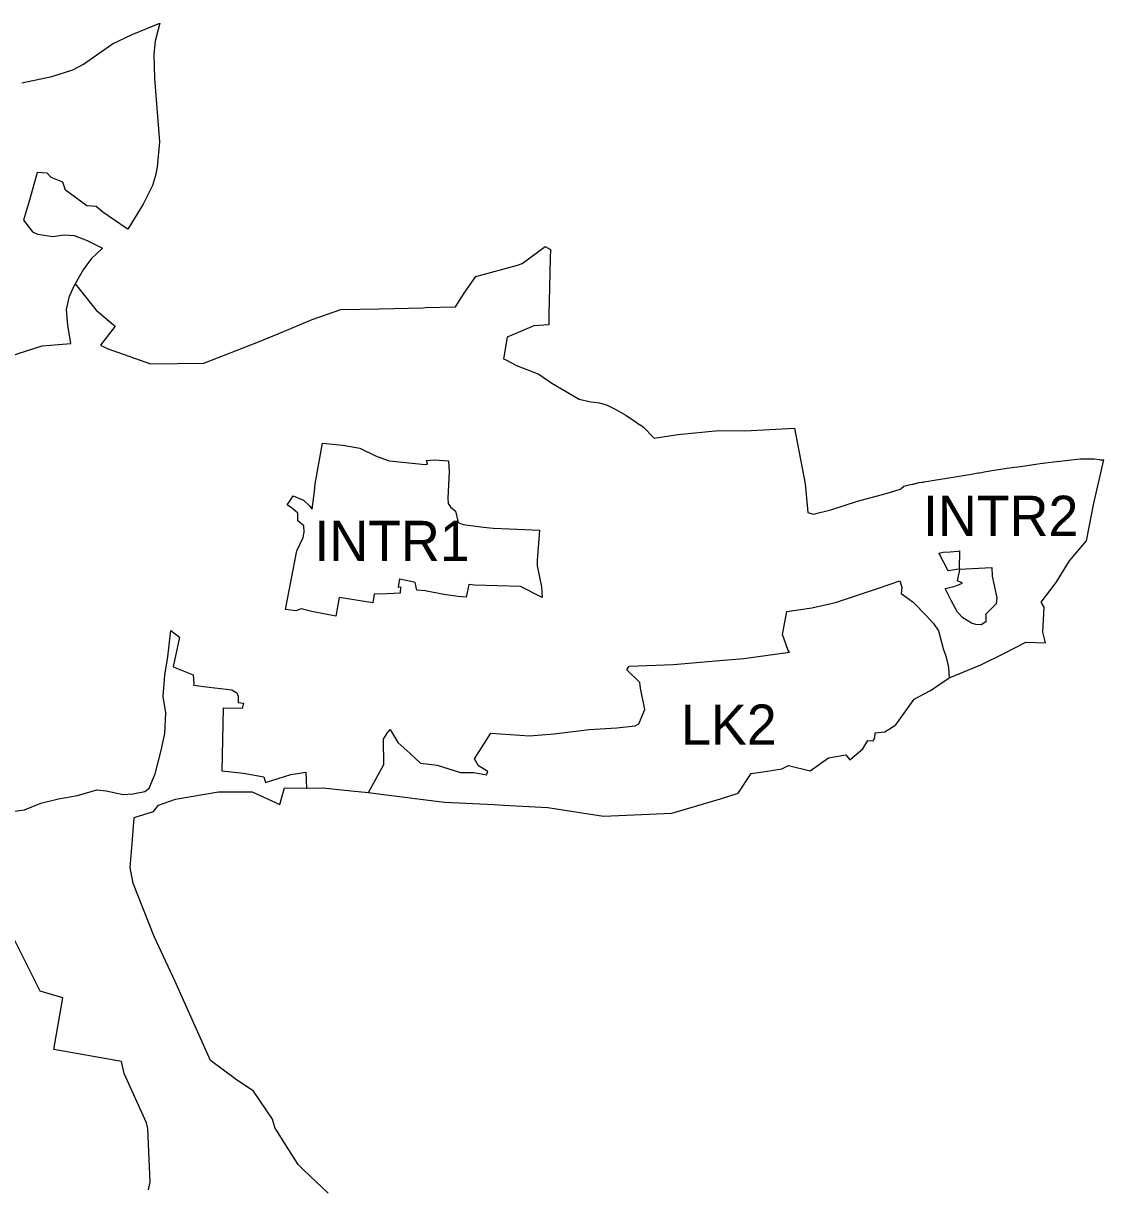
# Model space of a CAD drawing. Extents: x -754919 to -751903, y -1143879 to -1139906.
# Drawn here: x -753784 to -751903, y -1141930 to -1139906 of the extents above; entities that cross this region are included whole.
import ezdxf

# ---------------------------------------------------------------- set-up
doc = ezdxf.new("R2010")
doc.units = 0
for name, color, linetype in [('Vrstva 13', 7, 'Continuous'), ('Vrstva 2', 7, 'Continuous'), ('Vrstva 4', 7, 'Continuous'), ('Vrstva 6', 7, 'Continuous')]:
    doc.layers.add(name, color=color, linetype=linetype)

msp = doc.modelspace()

# ---------------------------------------------------------------- linework, layer by layer
at = {"layer": 'Vrstva 13'}
for p, q in [((-753594.49, -1139925.95), (-753546, -1139906.33)), ((-753546, -1139906.33), (-753554.18, -1139937.38)), ((-753679.34, -1139977.81), (-753628.6, -1139942.29)), ((-753628.6, -1139942.29), (-753594.49, -1139925.95)), ((-753554.18, -1139937.38), (-753556.53, -1139960.2)), ((-753556.53, -1139960.2), (-753555.59, -1140002.25)), ((-753697.41, -1139987.55), (-753679.34, -1139977.81)), ((-753786.41, -1140010.3), (-753733.98, -1139998.76)), ((-753733.98, -1139998.76), (-753697.41, -1139987.55)), ((-753555.59, -1140002.25), (-753546.66, -1140112.83)), ((-753546.66, -1140112.83), (-753550.87, -1140157.09)), ((-753759.52, -1140166.02), (-753773.33, -1140214.43)), ((-753742.36, -1140167.45), (-753759.52, -1140166.02)), ((-753550.87, -1140157.09), (-753553.62, -1140171.36)), ((-753735.49, -1140174.73), (-753742.36, -1140167.45)), ((-753715.04, -1140182.67), (-753735.49, -1140174.73)), ((-753710.41, -1140197.1), (-753715.04, -1140182.67)), ((-753553.62, -1140171.36), (-753559.2, -1140188.9)), ((-753673.16, -1140224.2), (-753710.41, -1140197.1)), ((-753559.2, -1140188.9), (-753575.24, -1140221.13)), ((-753773.33, -1140214.43), (-753783.31, -1140249.29)), ((-753656.91, -1140225.41), (-753673.16, -1140224.2)), ((-753645.46, -1140235.37), (-753656.91, -1140225.41)), ((-753575.24, -1140221.13), (-753602.16, -1140264.61)), ((-753604.73, -1140262.87), (-753645.46, -1140235.37)), ((-753783.31, -1140249.29), (-753768.02, -1140269.15)), ((-753602.16, -1140264.61), (-753604.73, -1140262.87)), ((-753768.02, -1140269.15), (-753759.37, -1140273.27)), ((-753759.37, -1140273.27), (-753732.61, -1140277.4)), ((-753732.61, -1140277.4), (-753712.47, -1140274.49)), ((-753712.47, -1140274.49), (-753695.07, -1140275.67)), ((-753695.07, -1140275.67), (-753672.72, -1140284.4)), ((-753672.72, -1140284.4), (-753646.26, -1140297.83)), ((-753646.26, -1140297.83), (-753665.53, -1140316.44)), ((-752915.15, -1140324.22), (-752874.93, -1140295.15)), ((-752874.93, -1140295.15), (-752866.09, -1140300.36)), ((-752866.09, -1140300.36), (-752866.42, -1140314.92)), ((-753665.53, -1140316.44), (-753679.47, -1140335.74)), ((-752996.14, -1140347.33), (-752923.33, -1140327.21)), ((-752923.33, -1140327.21), (-752915.15, -1140324.22)), ((-752866.42, -1140314.92), (-752867, -1140340.25)), ((-753679.47, -1140335.74), (-753693.42, -1140360)), ((-753016.17, -1140376.35), (-752996.14, -1140347.33)), ((-752867, -1140340.25), (-752868.14, -1140390.58)), ((-753693.42, -1140360), (-753684.23, -1140371.56)), ((-753684.23, -1140371.56), (-753657.16, -1140405.61)), ((-753031.34, -1140400.09), (-753016.17, -1140376.35)), ((-753657.16, -1140405.61), (-753626.85, -1140431.3)), ((-753280.74, -1140422.14), (-753230.77, -1140404.54)), ((-753230.77, -1140404.54), (-753164.62, -1140403.24)), ((-753164.62, -1140403.24), (-753087.86, -1140401.43)), ((-753087.86, -1140401.43), (-753084.06, -1140401.34)), ((-753084.06, -1140401.34), (-753031.34, -1140400.09)), ((-752868.14, -1140390.58), (-752868.6, -1140410.75)), ((-753336.01, -1140445.01), (-753280.74, -1140422.14)), ((-752868.6, -1140410.75), (-752869.07, -1140431.37)), ((-753624.11, -1140433.63), (-753649.36, -1140466.63)), ((-753626.85, -1140431.3), (-753624.11, -1140433.63)), ((-753377.25, -1140462.18), (-753336.01, -1140445.01)), ((-752894.72, -1140433.16), (-752941.33, -1140453)), ((-752869.07, -1140431.37), (-752894.72, -1140433.16)), ((-753649.36, -1140466.63), (-753638.09, -1140472.67)), ((-753469.49, -1140497.93), (-753377.25, -1140462.18)), ((-752941.33, -1140453), (-752947.7, -1140490.21)), ((-753638.09, -1140472.67), (-753562.69, -1140498.88)), ((-753562.69, -1140498.88), (-753469.49, -1140497.93)), ((-752947.7, -1140490.21), (-752943.5, -1140492.45)), ((-752943.5, -1140492.45), (-752924.98, -1140502.31)), ((-752924.98, -1140502.31), (-752885.95, -1140517.36)), ((-752885.95, -1140517.36), (-752863.41, -1140532.87)), ((-752863.41, -1140532.87), (-752815.79, -1140560.49)), ((-752815.79, -1140560.49), (-752795.75, -1140565.11)), ((-752795.75, -1140565.11), (-752780.29, -1140566.9)), ((-752780.29, -1140566.9), (-752767.16, -1140571.19)), ((-752767.16, -1140571.19), (-752753.13, -1140577.78)), ((-752753.13, -1140577.78), (-752734.43, -1140588.57)), ((-752734.43, -1140588.57), (-752716.77, -1140600.62)), ((-752716.77, -1140600.62), (-752713.69, -1140602.72)), ((-752713.69, -1140602.72), (-752707.09, -1140607.22)), ((-752707.09, -1140607.22), (-752703.83, -1140609.44)), ((-752703.83, -1140609.44), (-752685.4, -1140628.65)), ((-752527.68, -1140615.88), (-752441.03, -1140610.83)), ((-752441.03, -1140610.83), (-752422.64, -1140708.22)), ((-752685.4, -1140628.65), (-752644, -1140622.18)), ((-752644, -1140622.18), (-752572.98, -1140615.27)), ((-752572.98, -1140615.27), (-752527.68, -1140615.88)), ((-752013.19, -1140672.6), (-752007.81, -1140671.83)), ((-752007.81, -1140671.83), (-752004.62, -1140671.46)), ((-752004.62, -1140671.46), (-751943.59, -1140664.35)), ((-751943.59, -1140664.35), (-751919.21, -1140664.56)), ((-751919.86, -1140741.61), (-751902.51, -1140666.4)), ((-751919.21, -1140664.56), (-751910.79, -1140665.62)), ((-751910.79, -1140665.62), (-751908.26, -1140665.94)), ((-751908.26, -1140665.94), (-751902.51, -1140666.4)), ((-752147.19, -1140693.27), (-752129.95, -1140690.44)), ((-752129.95, -1140690.44), (-752124.87, -1140689.6)), ((-752124.87, -1140689.6), (-752120.42, -1140688.87)), ((-752120.42, -1140688.87), (-752118.97, -1140688.63)), ((-752118.97, -1140688.63), (-752115.46, -1140688.07)), ((-752115.46, -1140688.07), (-752110.72, -1140687.31)), ((-752110.72, -1140687.31), (-752093.14, -1140684.48)), ((-752093.14, -1140684.48), (-752074.94, -1140681.56)), ((-752074.94, -1140681.56), (-752071.19, -1140680.96)), ((-752071.19, -1140680.96), (-752062.09, -1140679.65)), ((-752062.09, -1140679.65), (-752047.56, -1140677.55)), ((-752047.56, -1140677.55), (-752020.55, -1140673.66)), ((-752020.55, -1140673.66), (-752013.19, -1140672.6)), ((-752422.64, -1140708.22), (-752417.81, -1140757.62)), ((-752255.48, -1140716.14), (-752250.42, -1140711.96)), ((-752250.42, -1140711.96), (-752239.12, -1140709.38)), ((-752239.12, -1140709.38), (-752235.95, -1140708.65)), ((-752235.95, -1140708.65), (-752234.49, -1140708.32)), ((-752234.49, -1140708.32), (-752224.01, -1140705.92)), ((-752224.01, -1140705.92), (-752219.4, -1140705.16)), ((-752219.4, -1140705.16), (-752217.26, -1140704.81)), ((-752217.26, -1140704.81), (-752215.45, -1140704.51)), ((-752215.45, -1140704.51), (-752211.97, -1140703.94)), ((-752211.97, -1140703.94), (-752207.74, -1140703.24)), ((-752207.74, -1140703.24), (-752201.24, -1140702.17)), ((-752201.24, -1140702.17), (-752197.74, -1140701.59)), ((-752197.74, -1140701.59), (-752164.99, -1140696.2)), ((-752164.99, -1140696.2), (-752147.19, -1140693.27)), ((-752331.56, -1140738.32), (-752281.55, -1140725.04)), ((-752281.55, -1140725.04), (-752257.08, -1140717.47)), ((-752257.08, -1140717.47), (-752255.48, -1140716.14)), ((-752377.84, -1140753), (-752331.56, -1140738.32)), ((-751932.42, -1140806.95), (-751919.86, -1140741.61)), ((-752417.81, -1140757.62), (-752408.61, -1140760.55)), ((-752408.61, -1140760.55), (-752377.84, -1140753)), ((-751961.94, -1140841.77), (-751932.42, -1140806.95)), ((-751985.4, -1140879.61), (-751961.94, -1140841.77)), ((-752011.65, -1140914.05), (-751985.4, -1140879.61)), ((-752006.25, -1140922.82), (-752011.65, -1140914.05)), ((-752008.67, -1140966.42), (-752006.25, -1140922.82)), ((-752003.83, -1140984.73), (-752008.67, -1140966.42)), ((-752076.66, -1141003.29), (-752038.37, -1140983.78)), ((-752038.37, -1140983.78), (-752003.83, -1140984.73)), ((-752116.68, -1141023), (-752076.66, -1141003.29)), ((-752171.56, -1141045.76), (-752116.68, -1141023)), ((-752204.35, -1141067.64), (-752171.56, -1141045.76)), ((-752232.88, -1141082.54), (-752204.35, -1141067.64)), ((-752264.77, -1141127.4), (-752232.88, -1141082.54)), ((-752283.9, -1141139.69), (-752264.77, -1141127.4)), ((-752321.87, -1141169.45), (-752313.28, -1141154.81)), ((-752313.28, -1141154.81), (-752304.08, -1141155.04)), ((-752304.08, -1141155.04), (-752301.13, -1141150.16)), ((-752301.13, -1141150.16), (-752300.56, -1141141.33)), ((-752300.56, -1141141.33), (-752283.9, -1141139.69)), ((-752344.63, -1141188.12), (-752321.87, -1141169.45)), ((-752413.63, -1141207.48), (-752382.04, -1141185.18)), ((-752382.04, -1141185.18), (-752351.86, -1141179.62)), ((-752351.86, -1141179.62), (-752344.63, -1141188.12)), ((-752539.4, -1141246.36), (-752516.76, -1141212.45)), ((-752516.76, -1141212.45), (-752491.94, -1141208.63)), ((-752491.94, -1141208.63), (-752462.88, -1141204.16)), ((-752462.88, -1141204.16), (-752451.7, -1141198.36)), ((-752451.7, -1141198.36), (-752413.63, -1141207.48)), ((-753337.06, -1141266.35), (-753329.01, -1141237.09)), ((-753329.01, -1141237.09), (-753290.83, -1141237.76)), ((-753290.83, -1141237.76), (-753262.57, -1141237.39)), ((-753262.57, -1141237.39), (-753212.76, -1141242.25)), ((-753548.27, -1141267.42), (-753518.61, -1141257)), ((-753518.61, -1141257), (-753443.73, -1141244.32)), ((-753443.73, -1141244.32), (-753385.57, -1141243.79)), ((-753385.57, -1141243.79), (-753337.06, -1141266.35)), ((-753212.76, -1141242.25), (-753182.94, -1141245.36)), ((-753182.94, -1141245.36), (-753161.13, -1141247.93)), ((-753161.13, -1141247.93), (-753050.75, -1141261.77)), ((-752654.45, -1141281.32), (-752569.69, -1141256.1)), ((-752569.69, -1141256.1), (-752539.4, -1141246.36)), ((-753591.07, -1141288.95), (-753557.15, -1141278.12)), ((-753557.15, -1141278.12), (-753548.27, -1141267.42)), ((-753050.75, -1141261.77), (-752963.8, -1141266.25)), ((-752963.8, -1141266.25), (-752947.47, -1141267.09)), ((-752947.47, -1141267.09), (-752870.43, -1141271.06)), ((-752870.43, -1141271.06), (-752773.66, -1141286.63)), ((-753593.74, -1141327.11), (-753591.63, -1141296.97)), ((-753591.63, -1141296.97), (-753591.07, -1141288.95)), ((-752773.66, -1141286.63), (-752654.45, -1141281.32)), ((-753598.07, -1141375.75), (-753593.74, -1141327.11)), ((-753594.98, -1141391.33), (-753598.07, -1141375.75)), ((-753593.37, -1141399.46), (-753594.98, -1141391.33)), ((-753592.94, -1141401.61), (-753593.37, -1141399.46)), ((-753556.28, -1141495.6), (-753592.94, -1141401.61)), ((-753519.49, -1141574.11), (-753556.28, -1141495.6)), ((-753457.91, -1141711.51), (-753519.49, -1141574.11)), ((-753414.97, -1141743.82), (-753457.91, -1141711.51)), ((-753382.94, -1141765.31), (-753414.97, -1141743.82)), ((-753349.69, -1141813.83), (-753382.94, -1141765.31)), ((-753347.97, -1141820.06), (-753349.69, -1141813.83)), ((-753346.28, -1141826.13), (-753347.97, -1141820.06)), ((-753345.7, -1141828.24), (-753346.28, -1141826.13)), ((-753329.73, -1141854.5), (-753345.7, -1141828.24)), ((-753305.04, -1141892.8), (-753329.73, -1141854.5)), ((-753303.66, -1141894.23), (-753305.04, -1141892.8)), ((-753296.14, -1141902.04), (-753303.66, -1141894.23)), ((-753252.88, -1141942.87), (-753296.14, -1141902.04))]:
    msp.add_line(p, q, dxfattribs=at)
at = {"layer": 'Vrstva 2'}
msp.add_line((-752153.47, -1140824.76), (-752154.23, -1140856.39), dxfattribs=at)
for points in [[(-753313.75, -1140728.99), (-753295.92, -1140736.15), (-753284.73, -1140746.9), (-753280.73, -1140752.22), (-753276.98, -1140721.56), (-753275.54, -1140708.13), (-753263.11, -1140637.4), (-753227.56, -1140640.75), (-753197.92, -1140646.11), (-753195.47, -1140647.24), (-753170.73, -1140659.07), (-753148.76, -1140667.4), (-753146.13, -1140668.09), (-753084.33, -1140674.13), (-753080.12, -1140673.74), (-753081.55, -1140667.22), (-753067.68, -1140666.26), (-753043.34, -1140668.11)], [(-753043.34, -1140668.11), (-753042.4, -1140686.86), (-753044.93, -1140732.78), (-753043.91, -1140742.05), (-753040.04, -1140748.29), (-753031.42, -1140755.55), (-753026.65, -1140775.18), (-753017.69, -1140778.75), (-752982.62, -1140783.31), (-752965.73, -1140785.21), (-752937.94, -1140786.41), (-752924.5, -1140787.04), (-752911.06, -1140787.35), (-752897.9, -1140787.97), (-752884.87, -1140788.59)], [(-753296.52, -1140801.56), (-753294.93, -1140791.98), (-753295.63, -1140781.28), (-753305.77, -1140772.11), (-753305.91, -1140759.01), (-753314.44, -1140751.47), (-753324.51, -1140744.47), (-753320.63, -1140738.5), (-753313.75, -1140728.99)], [(-752884.87, -1140788.59), (-752888.93, -1140841.16), (-752889.13, -1140850.97), (-752881.69, -1140887.43), (-752880.26, -1140905.84), (-752918.14, -1140886.54), (-752997.99, -1140884.58), (-753008.05, -1140883.34)], [(-753239.95, -1140938.18), (-753281.58, -1140930.1), (-753299.82, -1140925.45), (-753309.54, -1140929.26), (-753327.14, -1140926.46), (-753307.39, -1140824.44), (-753296.52, -1140801.56)], [(-752154.27, -1140856.42), (-752158.13, -1140857.28), (-752173.45, -1140859.58), (-752188.69, -1140830.22), (-752189.59, -1140828.48), (-752182.14, -1140827.07), (-752170.24, -1140826.27), (-752156.43, -1140824.97), (-752153.47, -1140824.76)], [(-752154.23, -1140856.39), (-752097.57, -1140853.76), (-752096.81, -1140868.44), (-752088.67, -1140906.23), (-752090.01, -1140917.06), (-752107.79, -1140934.64), (-752108.13, -1140948.01), (-752115.83, -1140953.69), (-752125.08, -1140953.05), (-752132.56, -1140950.41), (-752147.71, -1140940.93), (-752157.19, -1140931.45), (-752168.4, -1140910.83), (-752178.42, -1140890.27), (-752163.36, -1140886.9), (-752157.33, -1140884.24), (-752148.27, -1140880.81), (-752157.17, -1140876.99), (-752153.04, -1140857.92), (-752154.27, -1140856.42)], [(-753008.05, -1140883.34), (-753012.9, -1140905.38), (-753026.62, -1140903.89), (-753051.55, -1140900.48), (-753083.85, -1140894.51), (-753098.72, -1140892.92), (-753101.61, -1140879.94), (-753111.61, -1140877.49), (-753128.62, -1140873.67), (-753129.01, -1140873.58), (-753131.27, -1140887.71), (-753127.34, -1140887.31), (-753127.4, -1140898.4), (-753150.07, -1140899.22), (-753173.15, -1140900.28), (-753175.16, -1140914.98), (-753233.82, -1140905.99), (-753239.95, -1140938.18)]]:
    msp.add_lwpolyline(points, dxfattribs=at)
at = {"layer": 'Vrstva 4'}
for points in [[(-754261.71, -1140353.34), (-754226.5, -1140351.34), (-754164.77, -1140358.18), (-754121.98, -1140367.31), (-754067.73, -1140259.06), (-754010.66, -1140305.94), (-753990.23, -1140312.3), (-753952.78, -1140339.4), (-753940.29, -1140322.3), (-753927.9, -1140318.09), (-753908.58, -1140328.52), (-753872.87, -1140363.97), (-753848.15, -1140410.68), (-753827.69, -1140494.07), (-753792.76, -1140481.05), (-753751.18, -1140467.9), (-753700.94, -1140464.01), (-753706.63, -1140431.58), (-753708.59, -1140404.46), (-753703.24, -1140381.08), (-753693.42, -1140360)], [(-753182.94, -1141245.36), (-753155.96, -1141196.47), (-753156.86, -1141152.55), (-753150.42, -1141141.69), (-753145.15, -1141135.32), (-753132, -1141158.49), (-753110.24, -1141177.5), (-753092.35, -1141194.34), (-753063.08, -1141197.74), (-753022.57, -1141210.15), (-752999.65, -1141210.68), (-752977.5, -1141214.69), (-752974.84, -1141208.86), (-752991.4, -1141198.91), (-752998.19, -1141186.53), (-752969.72, -1141142.08), (-752902.28, -1141146.65), (-752859.27, -1141142.94), (-752798.58, -1141135.47), (-752750.2, -1141132.92), (-752718.28, -1141129.37), (-752712.22, -1141125.98), (-752701.48, -1141100.8), (-752709.42, -1141063.38), (-752710.1, -1141053.63), (-752732.91, -1141031.91), (-752728.83, -1141025.26), (-752651.63, -1141022.27), (-752578.69, -1141016.08), (-752529, -1141012.17), (-752449.77, -1141001.13), (-752452.14, -1140998.16), (-752461.79, -1140970.4), (-752454.22, -1140930.42), (-752411.02, -1140923.63), (-752369.59, -1140914.3), (-752294.91, -1140889.5), (-752257.86, -1140876.61), (-752254.15, -1140887.91), (-752255.13, -1140898.93), (-752247.32, -1140904.52), (-752234.52, -1140914.12), (-752211.42, -1140937.9), (-752198.89, -1140950.86), (-752190, -1140963.88), (-752182.25, -1140994.64), (-752176.81, -1141009.47), (-752172.59, -1141027.89), (-752171.56, -1141045.76)], [(-753609.94, -1141248.94), (-753593.45, -1141247.45), (-753572.23, -1141243.5), (-753564.57, -1141237.61), (-753554.14, -1141212.66), (-753543.98, -1141172.02), (-753537.25, -1141142.37), (-753535.63, -1141106.61), (-753540.31, -1141078.19), (-753537.63, -1141040.84), (-753532.14, -1141008.95), (-753526.83, -1140963.25), (-753512.16, -1140974.91), (-753523.17, -1141026.38), (-753487.83, -1141040.29)], [(-753487.83, -1141040.29), (-753487.09, -1141055.93), (-753487.34, -1141058.17), (-753460.19, -1141061.69), (-753420.97, -1141066.37), (-753412.31, -1141071.85), (-753409.94, -1141077.69), (-753409.78, -1141088.42), (-753400.51, -1141090.01), (-753402.9, -1141098.92), (-753435.94, -1141098.23), (-753438.15, -1141207.74), (-753400.29, -1141211.46), (-753364.83, -1141217.84), (-753361.99, -1141227.89), (-753318.21, -1141214.12), (-753291.67, -1141209.75), (-753290.83, -1141237.76)], [(-753807.44, -1141278.76), (-753781.77, -1141275.3), (-753753.36, -1141264.02), (-753722.6, -1141256.25), (-753689.75, -1141250.51), (-753655.95, -1141240.87), (-753639.75, -1141242.34), (-753609.94, -1141248.94)], [(-753715.11, -1141602.56), (-753754.56, -1141591.18), (-753805.66, -1141488.69)], [(-753565.73, -1141937.09), (-753562.91, -1141923.3), (-753567.33, -1141829.76), (-753569.37, -1141819.95), (-753608.1, -1141734.59), (-753613.17, -1141713.65), (-753730.93, -1141692.68), (-753715.11, -1141602.56)]]:
    msp.add_lwpolyline(points, dxfattribs=at)

# ---------------------------------------------------------------- texts
msp.add_text('LK2', height=70, dxfattribs=at).set_placement((-752638.54, -1141162.09))
at = {"layer": 'Vrstva 6'}
for s, p in [('INTR2', (-752217.2, -1140798.69)), ('INTR1', (-753276.89, -1140842.34))]:
    msp.add_text(s, height=70, dxfattribs=at).set_placement(p)

doc.saveas('drawing.dxf')
